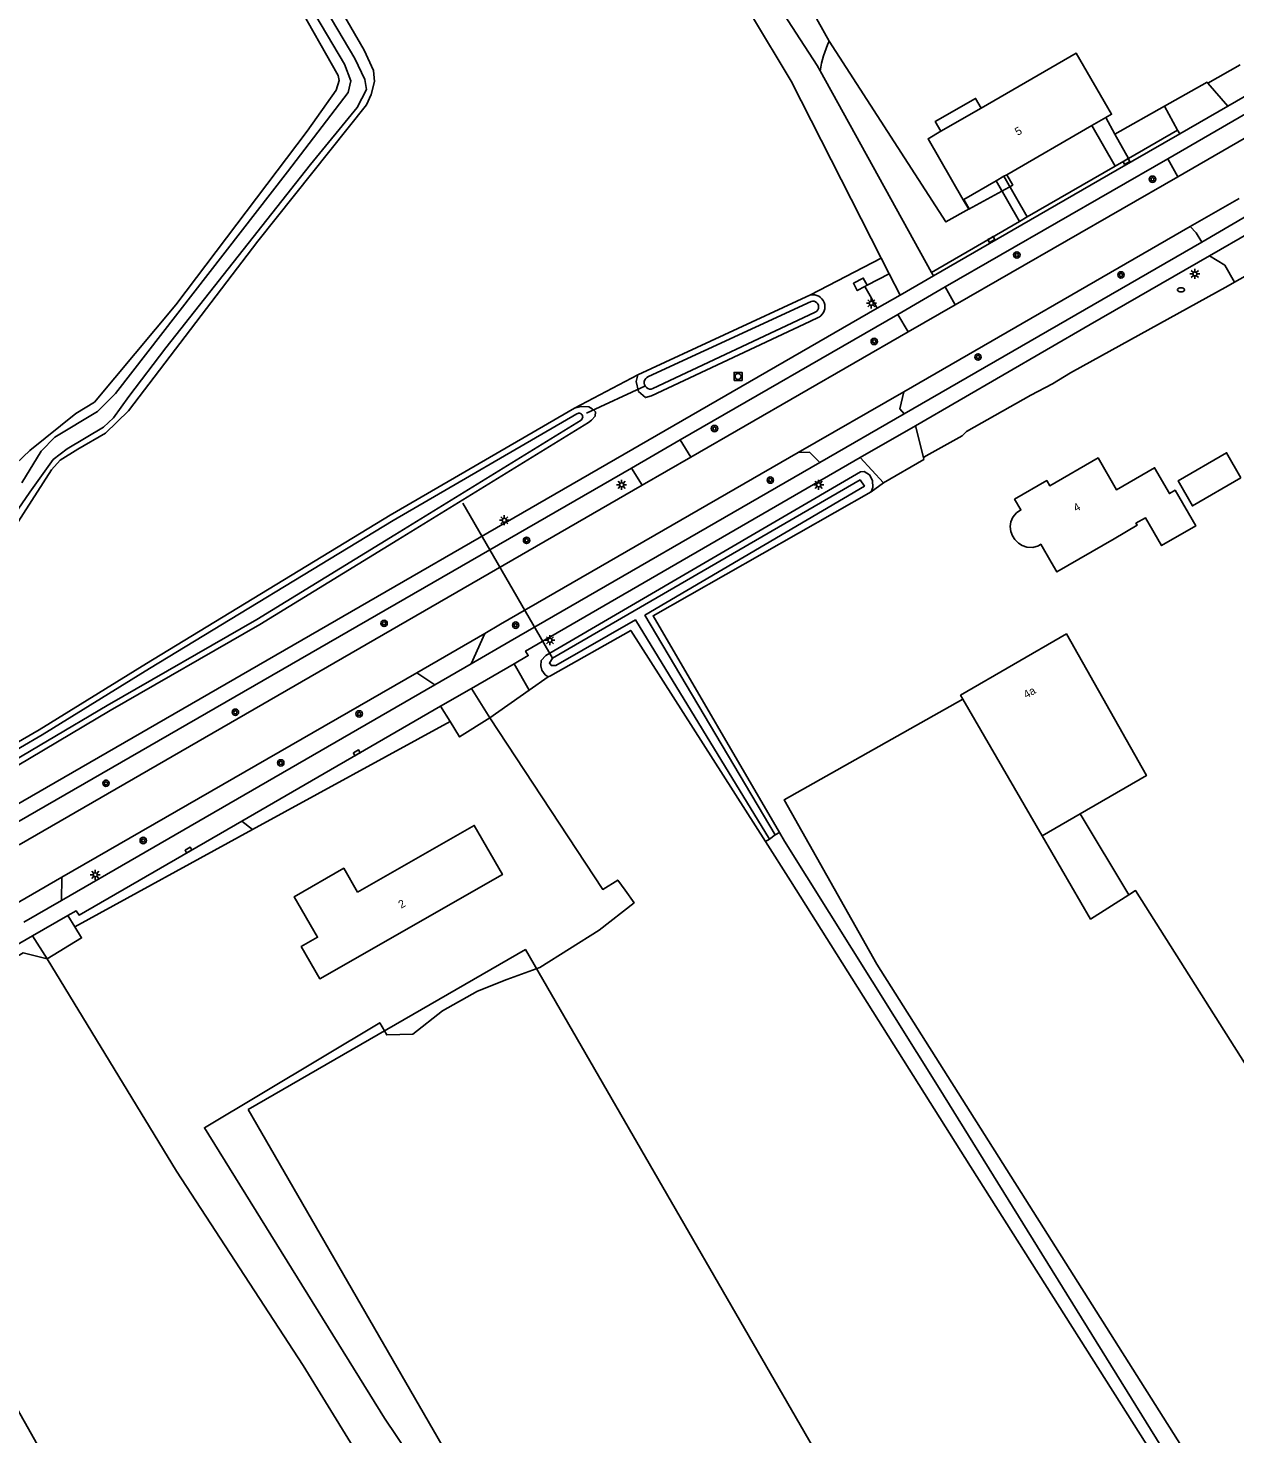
# Model space of a CAD drawing. Extents: x 137000 to 140001, y 403500 to 406000.
# Drawn here: x 139693.7 to 139844.4, y 403918.5 to 404094.1 of the extents above; entities that cross this region are included whole.
import ezdxf

# ---------------------------------------------------------------- set-up
doc = ezdxf.new("R2010")
doc.units = 0
for name, color, linetype in [('gg-afsc-erfafscheiding', 7, 'Continuous'), ('gg-afsc-hekwerk', 7, 'Continuous'), ('gg-anno-huisnummerreeks BGT', 7, 'Continuous'), ('gg-bbg-bijgebouw', 7, 'Continuous'), ('gg-bbg-hoofdgebouw', 7, 'Continuous'), ('gg-bbg-lage trafo', 7, 'Continuous'), ('gg-bbg-luifel en loopbrug', 7, 'Continuous'), ('gg-bbg-tussenscheiding', 7, 'Continuous'), ('gg-knt-bronhoudergrens', 7, 'Continuous'), ('gg-knt-verharding', 7, 'Continuous'), ('gg-knt-verharding nz', 7, 'Continuous'), ('gg-kntw-bovenkant insteek waterloop', 7, 'Continuous'), ('gg-kntw-waterlijn', 7, 'Continuous'), ('gg-kwrk-duiker nz buis', 7, 'Continuous'), ('gt-bbg-plantopografie pand', 7, 'Continuous'), ('gt-grn-groengrens', 7, 'Continuous'), ('gt-grn-vlakafsluiter', 7, 'Continuous'), ('gt-grn-weggrens', 7, 'Continuous'), ('gt-symb-boom', 7, 'Continuous'), ('gt-symb-brandkraan', 7, 'Continuous'), ('gt-symb-kolk', 7, 'Continuous'), ('gt-symb-lichtmast', 7, 'Continuous'), ('gt-symb-rioolschacht', 7, 'Continuous')]:
    doc.layers.add(name, color=color, linetype=linetype)

# ---------------------------------------------------------------- blocks, each defined once
blk = doc.blocks.new('gt0-LMAST')
at = {"layer": 'gt-symb-lichtmast'}
for p, q in [((-0.18, 0.17), (-0.45, 0.44)), ((-0.01, 0.25), (-0.01, 0.62)), ((0.17, 0.17), (0.44, 0.44)), ((-0.26, 0), (-0.63, 0)), ((-0.18, -0.18), (-0.45, -0.45)), ((-0.01, -0.25), (-0.01, -0.63)), ((0.44, -0.45), (0.17, -0.18)), ((0.24, 0), (0.62, 0))]:
    blk.add_line(p, q, dxfattribs=at)
blk.add_circle((-0.01, 0), 0.25, dxfattribs=at)
blk = doc.blocks.new('gt0-BOOM')
at = {"layer": 'gt-symb-boom'}
for radius in [0.4, 0.2]:
    blk.add_circle((0, 0), radius, dxfattribs=at)
blk = doc.blocks.new('gt0-RS')
at = {"layer": 'gt-symb-rioolschacht'}
blk.add_lwpolyline([(-0.5, -0.5), (0.5, -0.5), (0.5, 0.5), (-0.5, 0.5)], close=True, dxfattribs=at)
blk.add_circle((0, 0), 0.375, dxfattribs=at)
blk = doc.blocks.new('gt0-KOLK')
at = {"layer": 'gt-symb-kolk'}
blk.add_lwpolyline([(0, 0), (0.37, 0), (0.37, 0.4), (-0.38, 0.4), (-0.38, 0), (0, 0)], dxfattribs=at)
blk = doc.blocks.new('gt0-BR')
at = {"layer": 'gt-symb-brandkraan'}
for centre, radius, start, end in [((-0.24, 0), 0.206, 107.5669, 252.4331), ((0.6, -2.66), 3, 106.892, 107.5669), ((0, -0.69), 0.938, 73.108, 106.892), ((-0.6, -2.66), 3, 72.4331, 73.108), ((0.24, 0), 0.206, 287.567, 72.4331), ((0.6, 2.66), 3, 252.4331, 253.108), ((0, 0.69), 0.938, 253.108, 286.8921), ((-0.6, 2.66), 3, 286.8921, 287.567)]:
    blk.add_arc(centre, radius, start, end, dxfattribs=at)

msp = doc.modelspace()

# ---------------------------------------------------------------- linework, layer by layer
at = {"layer": 'gg-afsc-erfafscheiding'}
for p, q in [((139841.07, 404087.26), (139845.1, 404089.56)), ((139829.44, 404080.91), (139835.66, 404084.4)), ((139826.59, 404081.99), (139829.48, 404076.9)), ((139828.3, 404082.97), (139829.44, 404080.91)), ((139829.44, 404080.91), (139831.13, 404077.85)), ((139814.63, 404075.08), (139817.55, 404070)), ((139815.58, 404075.63), (139818.5, 404070.55)), ((139799.02, 404036.2), (139800.56, 404037.34)), ((139758.65, 404013.11), (139756.28, 404011.44)), ((139756.28, 404011.44), (139751.36, 404007.98)), ((139746.39, 404007.5), (139721.71, 403994.01)), ((139721.71, 403994.01), (139699.5, 403981.87))]:
    msp.add_line(p, q, dxfattribs=at)
for points in [[(139810.59, 404072.74), (139811.25, 404071.55), (139808.33, 404069.93), (139793.76, 404092.51)], [(139844.4, 404062.39), (139843.62, 404061.95), (139823.9, 404051.06), (139821.66, 404049.69), (139818.93, 404048.28), (139810.93, 404043.74), (139810.38, 404043.22), (139805.89, 404040.69), (139805.54, 404040.51)]]:
    msp.add_lwpolyline(points, dxfattribs=at)
at = {"layer": 'gg-afsc-hekwerk'}
for p, q in [((139845.1, 404089.56), (139841.07, 404087.26)), ((139843.62, 404061.95), (139844.4, 404062.39)), ((139823.9, 404051.06), (139843.62, 404061.95))]:
    msp.add_line(p, q, dxfattribs=at)
at = {"layer": 'gg-bbg-bijgebouw'}
msp.add_line((139825.11, 403995.96), (139820.38, 403993.22), dxfattribs=at)
for points in [[(139929.95, 403994.01), (139895.63, 404043.97), (139872.06, 404027.78), (139910.45, 403971.9), (139861.84, 403939.25), (139832.04, 403986.39), (139831.2, 403985.86)], [(139825.11, 403995.96), (139833.38, 404000.75), (139823.4, 404018.46), (139810.18, 404010.79), (139810.46, 404010.3)], [(139810.46, 404010.3), (139788.12, 403997.72), (139799.69, 403977.19), (139877.63, 403853.91), (139910.4, 403874.62), (139897.5, 403895.02), (139963.28, 403939.2), (139927.55, 403992.36), (139929.95, 403994.01)], [(139820.38, 403993.22), (139826.41, 403982.83), (139831.2, 403985.86)]]:
    msp.add_lwpolyline(points, dxfattribs=at)
at = {"layer": 'gg-bbg-hoofdgebouw'}
for p, q in [((139812.74, 404084.15), (139807.71, 404081.25)), ((139826.59, 404081.99), (139815.93, 404075.83)), ((139826.59, 404081.99), (139828.3, 404082.97)), ((139810.59, 404072.74), (139814.63, 404075.08)), ((139814.63, 404075.08), (139815.58, 404075.63)), ((139815.58, 404075.63), (139815.93, 404075.83)), ((139810.51, 404072.7), (139810.59, 404072.74))]:
    msp.add_line(p, q, dxfattribs=at)
for points in [[(139828.3, 404082.97), (139829.03, 404083.39), (139824.63, 404091.01), (139812.74, 404084.15)], [(139807.71, 404081.25), (139806.11, 404080.32), (139810.51, 404072.7)], [(139829.35, 404030.35), (139832.22, 404032.02), (139832.07, 404032.28), (139833.27, 404032.97), (139835.29, 404029.48), (139839.55, 404031.95), (139836.97, 404036.4), (139836.27, 404035.99), (139834.4, 404039.22), (139829.65, 404036.47), (139827.34, 404040.45), (139821.32, 404036.96), (139820.94, 404037.61), (139816.92, 404035.28), (139817.7, 404033.94), (139817.17, 404033.6), (139816.72, 404033.04), (139816.47, 404032.44), (139816.37, 404031.88), (139816.45, 404031.26), (139816.67, 404030.69), (139816.94, 404030.24), (139817.4, 404029.8), (139817.88, 404029.51), (139818.43, 404029.3), (139819.18, 404029.26), (139819.9, 404029.45), (139820.19, 404029.66), (139821.5, 404027.41), (139822.2, 404026.2), (139829.35, 404030.35)], [(139734.84, 403986.18), (139749.42, 403994.53), (139752.94, 403988.39), (139730.11, 403975.36), (139727.79, 403979.39), (139729.83, 403980.56), (139726.93, 403985.62), (139733.11, 403989.18), (139734.84, 403986.18)]]:
    msp.add_lwpolyline(points, dxfattribs=at)
at = {"layer": 'gg-bbg-lage trafo'}
msp.add_line((139798.21, 404061.85), (139798.5, 404062.01), dxfattribs=at)
msp.add_lwpolyline([(139798.21, 404061.85), (139797.27, 404061.36), (139796.79, 404062.27), (139798.02, 404062.92), (139798.5, 404062.01)], dxfattribs=at)
at = {"layer": 'gg-bbg-luifel en loopbrug'}
msp.add_line((139825.11, 403995.96), (139831.2, 403985.86), dxfattribs=at)
for points in [[(139812.74, 404084.15), (139812.04, 404085.36), (139807.01, 404082.46), (139807.71, 404081.25)], [(139810.51, 404072.7), (139811.19, 404071.52), (139816.68, 404074.54), (139815.93, 404075.83)], [(139845.2, 404037.96), (139843.4, 404041.08), (139837.34, 404037.57), (139839.14, 404034.45), (139845.2, 404037.96)]]:
    msp.add_lwpolyline(points, dxfattribs=at)
at = {"layer": 'gg-bbg-tussenscheiding'}
msp.add_line((139810.46, 404010.3), (139820.38, 403993.22), dxfattribs=at)
at = {"layer": 'gg-knt-bronhoudergrens'}
for points in [[(139751.36, 404007.98), (139765.47, 403986.53), (139767.33, 403987.69), (139768.28, 403986.45), (139769.39, 403984.86), (139765.02, 403981.45), (139757.6, 403976.77), (139753.48, 403975.26), (139749.82, 403973.83), (139745.46, 403971.37), (139741.73, 403968.43), (139738.47, 403968.35), (139737.6, 403969.86), (139715.69, 403956.76), (139738.2, 403920.46), (139752.73, 403898.83)], [(139696.04, 403977.87), (139693.05, 403978.6), (139669.28, 403964.55), (139669, 403962.25)], [(139696.04, 403977.87), (139712.23, 403951.34), (139728.04, 403927.04), (139746.43, 403897.08), (139749.93, 403891.59), (139752.38, 403888.15), (139754.43, 403885.37), (139757.08, 403882.26), (139759.33, 403880.28), (139761.18, 403878.89), (139763.92, 403877.97), (139770.14, 403869.04), (139769.67, 403866.13), (139735.5, 403845.43)]]:
    msp.add_lwpolyline(points, dxfattribs=at)
at = {"layer": 'gg-knt-verharding'}
for p, q in [((139888.29, 404110.18), (139843.56, 404084.39)), ((139790.81, 404097.86), (139793.76, 404092.51)), ((139792.64, 404088.79), (139806.52, 404063.62)), ((139841.07, 404087.26), (139843.56, 404084.39)), ((139835.66, 404084.4), (139837.29, 404081.41)), ((139845.77, 404083.43), (139836.05, 404077.83)), ((139843.56, 404084.39), (139837.56, 404080.93)), ((139831.13, 404077.85), (139837.29, 404081.41)), ((139837.29, 404081.41), (139837.56, 404080.93)), ((139829.75, 404076.43), (139837.56, 404080.93)), ((139808.24, 404061.81), (139836.05, 404077.83)), ((139829.48, 404076.9), (139831.13, 404077.85)), ((139836.05, 404077.83), (139837.32, 404075.57)), ((139817.82, 404069.55), (139829.75, 404076.43)), ((139818.5, 404070.55), (139829.48, 404076.9)), ((139809.49, 404059.55), (139837.32, 404075.57)), ((139838.86, 404069.34), (139803.09, 404048.71)), ((139806.52, 404063.62), (139817.55, 404070)), ((139806.77, 404063.18), (139817.82, 404069.55)), ((139817.55, 404070), (139818.5, 404070.55)), ((139840.31, 404067.41), (139845.95, 404070.67)), ((139840.31, 404067.41), (139803.14, 404045.95)), ((139846.46, 404068.69), (139841.28, 404065.7)), ((139801.26, 404063.46), (139800.27, 404065.41)), ((139847.42, 404064.1), (139844.4, 404062.39)), ((139801.26, 404063.46), (139802.62, 404060.79)), ((139806.77, 404063.18), (139802.62, 404060.79)), ((139806.52, 404063.62), (139806.77, 404063.18)), ((139799.77, 404059.14), (139802.62, 404060.79)), ((139808.24, 404061.81), (139802.33, 404058.37)), ((139809.49, 404059.55), (139808.24, 404061.81)), ((139687.78, 403994.55), (139799.77, 404059.14)), ((139802.33, 404058.37), (139775.14, 404042.69)), ((139803.63, 404056.21), (139802.33, 404058.37)), ((139803.63, 404056.21), (139776.49, 404040.55)), ((139792.59, 404039.86), (139803.14, 404045.95)), ((139797.62, 404040.48), (139804.52, 404044.46)), ((139805.54, 404040.51), (139804.52, 404044.46)), ((139775.14, 404042.69), (139769.04, 404039.17)), ((139776.49, 404040.55), (139775.14, 404042.69)), ((139691.18, 403994.25), (139769.04, 404039.17)), ((139769.04, 404039.17), (139770.37, 404037.02)), ((139800.56, 404037.34), (139797.62, 404040.48)), ((139692.54, 403992.1), (139770.37, 404037.02)), ((139749.04, 404014.72), (139750.73, 404018.51)), ((139744.48, 404012.08), (139749.04, 404014.72)), ((139754.39, 404014.72), (139749.05, 404011.63)), ((139742.23, 404013.61), (139697.89, 403988.04)), ((139744.48, 404012.08), (139742.23, 404013.61)), ((139697.85, 403985.16), (139744.48, 404012.08)), ((139749.05, 404011.63), (139745.21, 404009.42)), ((139751.36, 404007.98), (139749.05, 404011.63)), ((139745.21, 404009.42), (139720.39, 403995.07)), ((139745.21, 404009.42), (139746.39, 404007.5)), ((139697.85, 403985.16), (139697.89, 403988.04)), ((139697.85, 403985.16), (139693.12, 403982.42)), ((139694.23, 403980.73), (139698.64, 403983.28)), ((139698.64, 403983.28), (139699.5, 403981.87)), ((139666.02, 403964.46), (139694.23, 403980.73)), ((139696.04, 403977.87), (139694.23, 403980.73))]:
    msp.add_line(p, q, dxfattribs=at)
for points in [[(139800.27, 404065.41), (139788.99, 404087.52), (139784.04, 404095.78)], [(139835.66, 404084.4), (139840.97, 404087.38), (139841.07, 404087.26)], [(139840.31, 404067.41), (139839.62, 404068.55), (139838.86, 404069.34)], [(139841.28, 404065.7), (139826.37, 404057.1), (139804.52, 404044.46)], [(139841.28, 404065.7), (139843.18, 404064.54), (139844.4, 404062.39)], [(139803.14, 404045.95), (139802.59, 404046.56), (139803.09, 404048.71)], [(139750.73, 404018.51), (139752.71, 404019.66), (139789.9, 404041.1)], [(139792.59, 404039.86), (139791.31, 404041.15), (139789.9, 404041.1)], [(139749.04, 404014.72), (139753.91, 404017.53), (139792.59, 404039.86)], [(139797.62, 404040.48), (139755.83, 404016.3), (139756.16, 404015.74), (139754.39, 404014.72)], [(139800.56, 404037.34), (139805.6, 404040.26), (139805.54, 404040.51)], [(139751.36, 404007.98), (139747.57, 404005.58), (139746.39, 404007.5)], [(139720.39, 403995.07), (139700.05, 403983.32), (139699.67, 403983.87), (139698.64, 403983.28)], [(139696.04, 403977.87), (139700.36, 403980.47), (139699.5, 403981.87)]]:
    msp.add_lwpolyline(points, dxfattribs=at)
msp.add_arc((139804.18, 404087.34), 11.63, 153.6102, 172.8813, dxfattribs=at)
at = {"layer": 'gg-knt-verharding nz'}
for p, q in [((139847.49, 404081.43), (139837.32, 404075.57)), ((139844.98, 404072.87), (139838.86, 404069.34)), ((139803.63, 404056.21), (139809.49, 404059.55)), ((139803.09, 404048.71), (139789.9, 404041.1)), ((139776.49, 404040.55), (139770.37, 404037.02)), ((139742.23, 404013.61), (139750.73, 404018.51)), ((139697.89, 403988.04), (139689.49, 403983.2))]:
    msp.add_line(p, q, dxfattribs=at)
msp.add_lwpolyline([(139792.64, 404088.79), (139792.26, 404089.47), (139786.99, 404097.54)], dxfattribs=at)
at = {"layer": 'gg-kntw-bovenkant insteek waterloop'}
msp.add_line((139769.85, 404050.81), (139791.43, 404060.8), dxfattribs=at)
for points in [[(139692.2, 404039.73), (139693.87, 404041.36), (139699.64, 404046), (139701.97, 404047.42), (139712.14, 404059.58), (139728.53, 404081.25), (139732.17, 404086.41), (139732.55, 404087.62), (139732.43, 404088.22), (139727.11, 404097.56), (139701.01, 404141.46), (139700.5, 404142.39), (139700.55, 404143.88), (139701.19, 404144.89), (139710.19, 404151.43), (139713.42, 404153.46), (139713.79, 404154.48), (139714.09, 404157.18), (139709.9, 404166.37), (139701.55, 404189.15), (139699.12, 404197.27), (139698.66, 404202.42)], [(139717.05, 404157.47), (139717.61, 404155.98), (139717.76, 404154.82), (139717.77, 404153.66), (139717.58, 404151.65), (139716.37, 404150.42), (139706.26, 404144.03), (139705.75, 404143.21), (139715.7, 404125.82), (139735.64, 404091.41), (139736.82, 404088.85), (139736.97, 404087.49), (139736.55, 404085.85), (139735.97, 404084.57), (139722.37, 404067.51), (139706.21, 404046.33), (139703.34, 404043.54), (139699.88, 404041.54), (139697.68, 404040.18), (139696.61, 404038.95), (139688.52, 404026.4)], [(139769.85, 404050.81), (139769.66, 404050), (139769.93, 404048.75), (139770.79, 404047.99), (139771.56, 404048.19), (139791.33, 404057.49), (139792.48, 404058.04)], [(139761.95, 404046.65), (139762.78, 404046.85), (139763.71, 404046.84), (139764.16, 404046.59), (139764.56, 404046.21), (139764.52, 404045.67), (139764.08, 404045.15), (139763.7, 404044.87), (139739.88, 404030.2), (139722.63, 404019.63), (139703.92, 404008.87), (139688.96, 404000.03), (139688.07, 403999.59), (139687.32, 403999.66), (139686.58, 404000.42), (139686.47, 404001.1), (139686.67, 404001.62)], [(139761.95, 404046.65), (139738.9, 404033.29), (139708.46, 404014.76), (139695.07, 404006.48), (139686.67, 404001.62)], [(139758.65, 404013.11), (139758.28, 404013.34), (139757.85, 404013.92), (139757.72, 404014.46), (139757.79, 404015.15), (139758.37, 404015.76), (139797.67, 404038.71), (139798.12, 404038.75), (139798.79, 404038.35), (139799.17, 404037.64), (139799.19, 404036.75), (139799.02, 404036.2)], [(139787.54, 403993.65), (139771.76, 404020.73), (139799.02, 404036.2)], [(139758.65, 404013.11), (139758.92, 404013.21), (139768.97, 404018.89), (139785.79, 403992.51)], [(139876.87, 403850.4), (139835.17, 403917.02), (139807.48, 403961.7), (139788.17, 403992.57), (139787.54, 403993.65)], [(139785.79, 403992.51), (139788.94, 403987.59), (139811.39, 403951.89), (139837.7, 403910.44)], [(139735.5, 403845.43), (139717.23, 403876.92), (139698.54, 403910.55), (139679.07, 403945.07), (139669, 403962.25)]]:
    msp.add_lwpolyline(points, dxfattribs=at)
msp.add_arc((139791.72, 404059.33), 1.5, 300.5756, 100.905, dxfattribs=at)
at = {"layer": 'gg-kntw-waterlijn'}
for p, q in [((139791.5, 404060), (139771.18, 404050.6)), ((139771.73, 404049.1), (139791.91, 404058.6)), ((139786.99, 403993.33), (139786.28, 403992.82))]:
    msp.add_line(p, q, dxfattribs=at)
for points in [[(139699.3, 404200.79), (139699.74, 404197.13), (139701.33, 404192.29), (139708.49, 404173.55), (139711.48, 404163.98), (139714.56, 404157.34), (139714.92, 404154.63), (139713.76, 404152.14), (139702.97, 404144.97), (139702.06, 404143.36), (139702.07, 404141.42), (139705.27, 404136.79), (139733.2, 404089.66), (139734, 404087.57), (139733.68, 404086.09), (139726.09, 404076.17), (139704.59, 404048.5), (139702.35, 404046.26), (139697.03, 404043.03), (139695.29, 404041.28), (139692.89, 404037.32)], [(139688.65, 404028.57), (139693.87, 404036.18), (139696.82, 404040.23), (139698.56, 404041.59), (139703.08, 404044.3), (139704.35, 404045.47), (139706.27, 404048.12), (139710.9, 404054.19), (139728.97, 404077.09), (139734.78, 404084.23), (139735.93, 404086.46), (139735.75, 404087.71), (139734.5, 404090.34), (139725.06, 404106.27), (139704.17, 404143.14), (139704.37, 404143.66), (139705.38, 404144.97), (139710.24, 404148), (139714.43, 404150.38), (139715.9, 404151.88), (139716.68, 404153.75), (139716.65, 404156.19), (139716.18, 404157.84)], [(139762.75, 404045.16), (139739.49, 404030.84), (139722.25, 404020.27), (139703.54, 404009.52), (139688.6, 404000.69), (139687.93, 404000.36), (139687.66, 404000.38), (139687.29, 404000.77), (139687.24, 404001.02), (139687.27, 404001.1), (139695.45, 404005.83), (139708.85, 404014.12), (139739.29, 404032.64), (139762.23, 404045.94)], [(139786.28, 403992.82), (139769.55, 404020.2), (139759.61, 404014.5), (139759.05, 404014.5), (139758.8, 404014.8), (139759.19, 404015.41), (139797.62, 404037.7), (139798.16, 404036.92), (139770.74, 404020.78), (139786.99, 403993.33)]]:
    msp.add_lwpolyline(points, dxfattribs=at)
for centre, radius, start, end in [((139791.7, 404059.3), 0.73, 286.3075, 106.4672), ((139771.44, 404049.84), 0.799, 108.7621, 291.2838), ((139762.49, 404045.56), 0.469, 303.036, 124.7167)]:
    msp.add_arc(centre, radius, start, end, dxfattribs=at)
at = {"layer": 'gg-kwrk-duiker nz buis'}
for p, q in [((139763.43, 404046.04), (139770.81, 404049.46)), ((139759.19, 404015.41), (139747.97, 404034.78))]:
    msp.add_line(p, q, dxfattribs=at)
at = {"layer": 'gt-bbg-plantopografie pand'}
msp.add_lwpolyline([(139721.17, 403959.01), (139755.8, 403979.02), (139800.32, 403901.96), (139765.68, 403881.95), (139721.17, 403959.01)], dxfattribs=at)
at = {"layer": 'gt-grn-groengrens'}
for p, q in [((139800.27, 404065.41), (139791.43, 404060.8)), ((139769.85, 404050.81), (139761.95, 404046.65))]:
    msp.add_line(p, q, dxfattribs=at)
at = {"layer": 'gt-grn-vlakafsluiter'}
for p, q in [((139786.99, 403993.33), (139787.54, 403993.65)), ((139786.28, 403992.82), (139785.79, 403992.51))]:
    msp.add_line(p, q, dxfattribs=at)
at = {"layer": 'gt-grn-weggrens'}
for p, q in [((139798.5, 404062.01), (139801.26, 404063.46)), ((139799.77, 404059.14), (139798.21, 404061.85)), ((139754.39, 404014.72), (139756.28, 404011.44)), ((139721.71, 403994.01), (139720.39, 403995.07))]:
    msp.add_line(p, q, dxfattribs=at)

# ---------------------------------------------------------------- block references
at = {"layer": 'gt-symb-boom'}
for p in [(139834.15, 404075.26), (139817.2, 404065.8), (139830.21, 404063.31), (139799.38, 404055), (139812.35, 404053.05), (139779.43, 404044.11), (139786.4, 404037.67), (139755.95, 404030.14), (139738.15, 404019.77), (139754.59, 404019.55), (139719.57, 404008.67), (139735.03, 404008.46), (139725.24, 404002.34), (139703.4, 403999.79), (139708.06, 403992.64)]:
    msp.add_blockref('gt0-BOOM', p, dxfattribs=at)
at = {"layer": 'gt-symb-brandkraan'}
msp.add_blockref('gt0-BR', (139837.7, 404061.45), dxfattribs=at)
at = {"layer": 'gt-symb-kolk'}
for p, rotation in [((139830.79, 404077.65), -149.9648639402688), ((139813.91, 404067.9), -149.9648639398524), ((139734.84, 404003.42), 30.021162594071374), ((139713.81, 403991.27), 30.021162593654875)]:
    msp.add_blockref('gt0-KOLK', p, dxfattribs=dict(at, rotation=rotation))
at = {"layer": 'gt-symb-lichtmast'}
for p in [(139839.45, 404063.43), (139799.03, 404059.76), (139767.83, 404037.08), (139792.45, 404037.08), (139753.18, 404032.65), (139758.88, 404017.66), (139702.07, 403988.36)]:
    msp.add_blockref('gt0-LMAST', p, dxfattribs=at)
at = {"layer": 'gt-symb-rioolschacht'}
msp.add_blockref('gt0-RS', (139782.37, 404050.62), dxfattribs=at)

# ---------------------------------------------------------------- texts
at = {"layer": 'gg-anno-huisnummerreeks BGT'}
for s, rotation, p in [('5', 30, (139817.31, 404080.67)), ('4', 30.1, (139824.61, 404033.67)), ('4a', 30.1, (139818.38, 404010.34)), ('2', 29.8, (139740.28, 403984.11))]:
    msp.add_text(s, height=1, rotation=rotation, dxfattribs=at).set_placement(p)

doc.saveas('drawing.dxf')
